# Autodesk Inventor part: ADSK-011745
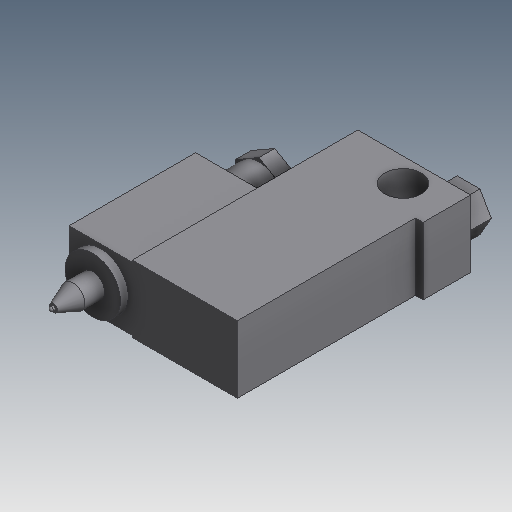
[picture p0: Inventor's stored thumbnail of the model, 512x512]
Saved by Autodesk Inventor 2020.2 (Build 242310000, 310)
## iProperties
Created: 1999-08
Part Number: ADSK-011745
Material: Pearson HRS
Document SubType Name: Modeling
Designer: Autodesk
Density: 7.83 g/cm^3
Appearance: Métal - Acier
Mass: 1141.06 g
Surface Area: 220.479 cm^2
Volume: 145.73 cm^3
Control State: 0
Master: False
Checked Out: False
Shininess: 0.0
Length Units: 11272
Angle Units: 11279
Time Units: 11290
Mass Units: 11286
Length Display Precision: 3
Angle Display Precision: 2
Compacted: True
Dimensions: 1,1x4,7x2,8 in
Mass: 2,516 lb
VLT_Material: Pearson HRS
Density: 0.0
Volumn: 0.0
Area: 0.0
PropertySet Name: Model Information
Author: Autodesk
Revision Number: -
Title: ADSK-011745
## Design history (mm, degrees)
node "Extrusion1" dims "d1" = 1.5875, "d2" = 0
workplane "Work Plane1"
node "Revolution1" dims "d84" = 90 deg
node "Extrusion2" dims "d11" = 7.9375, "d12" = 0
node "Extrusion3" dims "d14" = 3.175, "d15" = 0
node "Extrusion6" dims "d24" = 50.8, "d25" = 0
node "Extrusion7" dims "d28" = 71.4375, "d29" = 0
node "Extrusion8" dims "d32" = 19.05, "d33" = 0
node "Hole1" dims "d35" = 14.6812, "d36" = 9.525, "d37" = 6.35, "d38" = 60 deg, "d39" = 10.3632, "d40" = 118 deg
node "Extrusion9" dims "d54" = 9.525, "d55" = 0
node "Extrusion10" dims "d64" = 6.35, "d65" = 0
node "Extrusion11" dims "d67" = 12.7, "d68" = 0
node "Extrusion12" dims "d71" = 6.35, "d72" = 0
node "Fillet2" dims "d82" = 0.79375
node "Solide1"
node "Corps solides"
node "Corps surfaciques"
sketch "Sketch2"
  geometry: C1 r 0.794 at (0, 0) reference; C2 r 1.587 at (0, 0)
  constraints: 1 centre point, 1 coincident
  dimensions: "d4" = 3.175 diameter of C2
sketch "Sketch3"
  geometry: C1 r 4.763 at (0, 0); C2 r 1.587 at (0, 0) reference
  constraints: 1 centre point, 1 concentric
  dimensions: "d6" = 9.525 diameter of C1
sketch "Sketch1"
  geometry: C1 r 0.794 at (0, 0); 1 further point
  constraints: 1 centre point, 1 coincident
  dimensions: "d0" = 1.5875 diameter of C1
sketch "Sketch4"
  geometry: C1 r 4.763 at (0, 0); C2 r 4.763 at (0, 0); C3 r 4.763 at (0, 0) reference
  constraints: 2 centre point, 1 coincident
sketch "Sketch5"
  geometry: C1 r 4.763 at (0, 0) reference; C2 r 11.112 at (0, 0)
  constraints: 1 centre point, 1 coincident
  dimensions: "d13" = 22.225 diameter of C2
sketch "Sketch6"
  geometry: L1 (-12.7, -12.7)-(12.7, -12.7); L2 (12.7, -12.7)-(12.7, 12.7); L3 (12.7, 12.7)-(-12.7, 12.7); L4 (-12.7, 12.7)-(-12.7, -12.7); L5 (0, 12.7)-(0, -12.7); L6 (-12.7, 0)-(12.7, 0); C1 r 11.112 at (0, 0) reference
  constraints: 12 end point, 6 midpoint, 2 parallel, 1 horizontal, 1 perpendicular
  dimensions: "d22" = 25.4 distance of L2.end L3.end; "d23" = 25.4 distance of L3.end L1.start
sketch "Sketch8"
  geometry: L1 (12.7, 12.7)-(12.7, -12.7) reference; L2 (12.7, -13.462)-(54.864, -13.462); L3 (54.864, -13.462)-(54.864, 13.462); L4 (54.864, 13.462)-(12.7, 13.462); L5 (12.7, 13.462)-(12.7, -13.462); L6 (0, 0)-(54.864, 0); C1 r 11.112 at (0, 0) reference
  constraints: 10 end point, 2 horizontal, 2 parallel, 1 midpoint, 1 perpendicular, 1 point on line
  dimensions: "d26" = 26.924 distance of L2.end L3.end; "d27" = 42.164 distance of L3.end L4.end
sketch "Sketch9"
  geometry: L1 (-12.7, 13.462)-(-57.944, 13.462); L2 (-57.944, 13.462)-(-57.944, -13.462); L3 (-57.944, -13.462)-(-12.7, -13.462); L4 (-12.7, -13.462)-(-12.7, 13.462)
  constraints: 8 end point, 2 parallel, 1 horizontal, 1 perpendicular
  dimensions: "d30" = 26.924 distance of L1.end L2.end (= d26); "d31" = 45.24375 distance of L2.end L3.end
sketch "Sketch10"
  geometry: L1 (0, 0)-(0, 90.487) reference; L2 (45.244, 71.437)-(45.244, 90.487) reference; L3 (45.244, 80.962)-(0, 80.963); L4 (0, 50.8)-(-25.4, 50.8) reference; L5 (-25.4, 0)-(-25.4, 50.8) reference; L6 (-25.4, 0)-(0, 0) reference; 2 further points
  constraints: 2 end point, 2 point on line, 1 midpoint, 1 perpendicular
  dimensions: "d34" = 40.386 horizontal distance of point (27.686, 80.963) point (-12.7, -20.6)
sketch "Sketch11"
  geometry: L1 (-12.7, 13.462)-(-12.7, -13.462) reference; L2 (-57.944, -13.462)-(-57.944, 13.462) reference; L3 (-43.042, 7.937)-(-52.208, -7.938); L4 (-43.042, -7.938)-(-52.208, 7.938); L5 (-38.46, 0)-(-56.79, 0); L6 (-52.208, 7.938)-(-56.79, 0); L7 (-56.79, 0)-(-52.208, -7.938); L8 (-52.208, -7.938)-(-43.042, -7.938); L9 (-38.46, 0)-(-43.042, 7.937); L10 (-43.042, 7.937)-(-52.208, 7.938); L11 (-43.042, -7.938)-(-38.46, 0); L12 (-57.944, 0)-(-31.75, 0); 1 further point
  constraints: 20 end point, 6 parallel, 4 midpoint, 1 collinear, 1 point on line
  dimensions: "d47" = 60 deg angle of L4 L5; "d48" = 60 deg angle of L3 L5; "d53" = 34.925 distance from line of point (-47.625, 0) L1; "d56" = 15.875 distance between parallel lines of L10 L8
sketch "Sketch12"
  geometry: L1 (-12.7, 13.462)-(-12.7, -13.462) reference; L2 (-12.7, -13.462)-(-57.944, -13.462) reference; L3 (-18.559, 6.35)-(-25.891, -6.35); L4 (-25.891, 6.35)-(-18.559, -6.35); L5 (-29.557, 0)-(-14.893, 0); L6 (-18.559, 6.35)-(-25.891, 6.35); L7 (-25.891, 6.35)-(-29.557, 0); L8 (-29.557, 0)-(-25.891, -6.35); L9 (-25.891, -6.35)-(-18.559, -6.35); L10 (-18.559, -6.35)-(-14.893, 0); L11 (-14.893, 0)-(-18.559, 6.35); L12 (-12.7, 0)-(-22.225, 0)
  constraints: 20 end point, 6 equal length, 2 midpoint, 1 collinear, 1 parallel
  dimensions: "d60" = 60 deg angle of L3 L5; "d62" = 9.525 distance from line of L12.end L1; "d63" = 12.7 distance between parallel lines of L9 L6
sketch "Sketch13"
  geometry: C1 r 9.525 at (0, 0)
  constraints: 1 centre point
  dimensions: "d66" = 19.05 diameter of C1
sketch "Sketch14"
  geometry: L1 (8.249, -4.763)-(-8.249, 4.763); L2 (8.249, 4.763)-(-8.249, -4.763); L3 (0, -9.525)-(0, 10.999); L4 (-9.525, 5.499)-(-9.525, -5.499); L5 (-9.525, -5.499)-(0, -10.999); L6 (0, -10.999)-(9.525, -5.499); L7 (9.525, -5.499)-(9.525, 5.499); L8 (9.525, 5.499)-(0, 10.999); L9 (-9.525, 5.499)-(0, 10.999); C1 r 9.525 at (0, 0)
  constraints: 18 end point, 6 parallel, 5 tangent, 2 midpoint, 1 centre point, 1 point on line, 1 vertical, 1 other
  dimensions: "d69" = 60 deg angle of L2 L3; "d70" = 60 deg angle of L1 L3; "d81" = 19.05 distance between parallel lines of L5 L8
sketch "Sketch17"
  geometry: L1 (-0.794, 0)-(-0.794, -1.587) reference; L2 (-0.794, -1.587)-(-1.637, -1.587); L3 (-1.637, -1.587)-(-4.762, -9.488); L4 (-4.762, -9.488)-(0, -9.488); L5 (0, -9.488)-(0, -1.587); L6 (0, -1.587)-(-1.637, -1.587); L7 (0, -1.587)-(0, 0)
  constraints: 12 end point, 3 perpendicular, 1 collinear, 1 parallel
  dimensions: "d83" = 4.7625 distance of L3.end L4.end
other parameters: "d5" = -9.525
